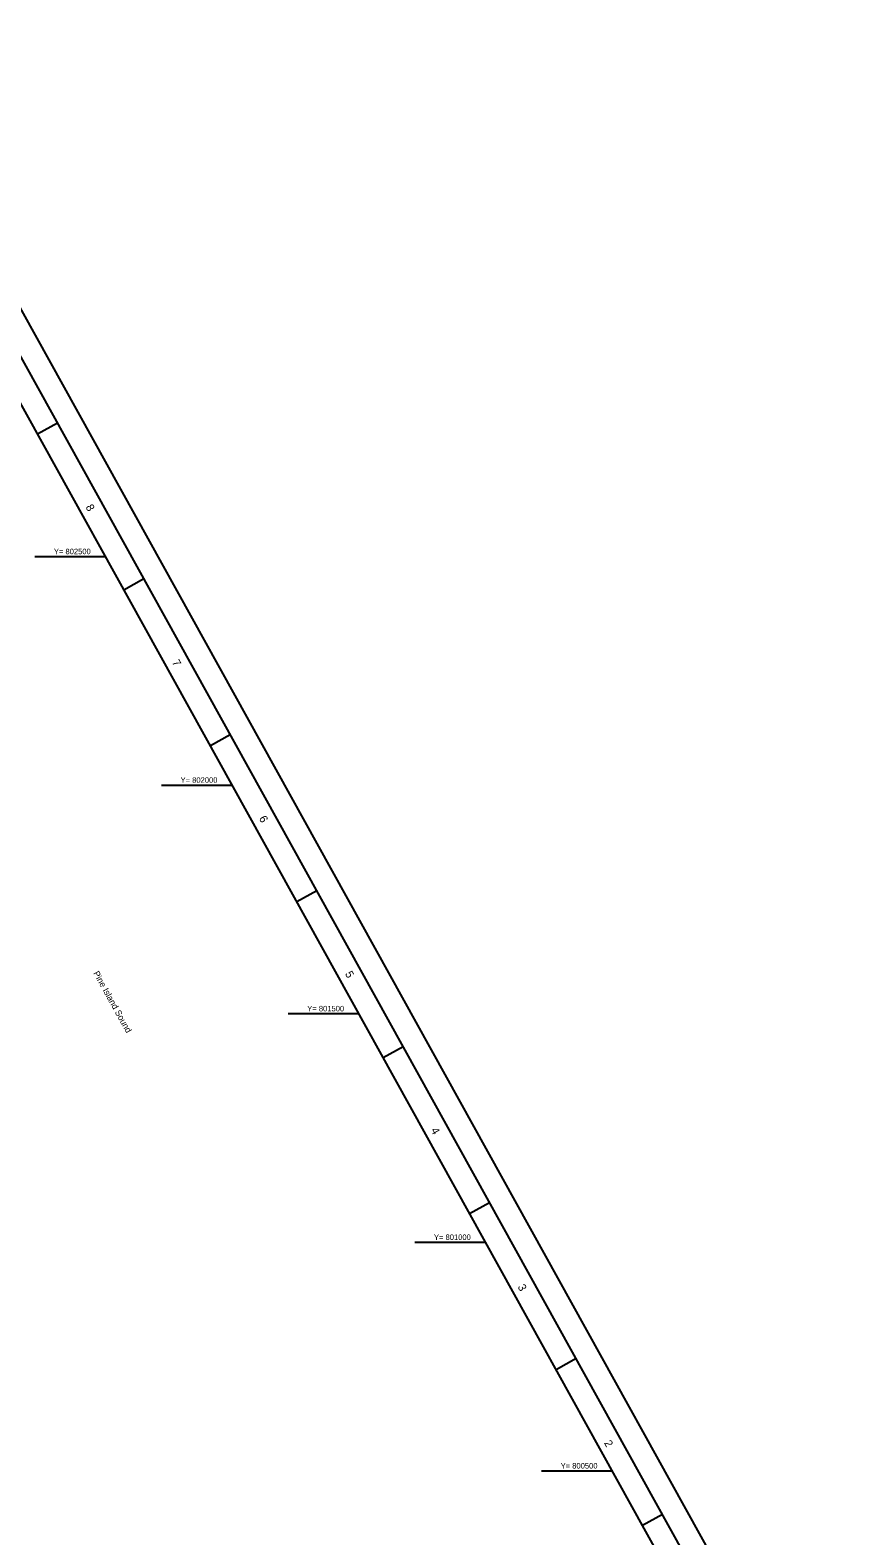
# Model space of a CAD drawing. Extents: x 601234 to 606341, y 798155 to 803651.
# Drawn here: x 604567 to 606341, y 800358 to 803651 of the extents above; entities that cross this region are included whole.
import ezdxf

# ---------------------------------------------------------------- set-up
doc = ezdxf.new("R2010")
doc.units = 0
for name, color, linetype in [('G-ANNO-NPLT', 7, 'Continuous'), ('G-ANNO-TTLB', 7, 'Continuous'), ('V-SITE-WATR', 7, 'Continuous'), ('V-TOPO-COOR-STAT', 7, 'Continuous')]:
    doc.layers.add(name, color=color, linetype=linetype)

msp = doc.modelspace()

# ---------------------------------------------------------------- linework, layer by layer
at = {"layer": 'G-ANNO-NPLT'}
msp.add_lwpolyline([(604207.8, 803651.4), (606341.2, 799803.3), (603367.7, 798154.7), (601234.2, 802002.9)], close=True, dxfattribs=at)
at = {"layer": 'G-ANNO-TTLB'}
for p, q in [((604627.1, 802791.9), (604583.4, 802767.7)), ((604627.1, 802791.9), (604583.4, 802767.7)), ((604816.2, 802450.9), (604772.5, 802426.6)), ((605005.3, 802109.8), (604961.6, 802085.5)), ((605194.4, 801768.7), (605150.7, 801744.4)), ((605383.5, 801427.6), (605339.8, 801403.3)), ((605572.6, 801086.5), (605528.9, 801062.3)), ((605761.7, 800745.4), (605718, 800721.2)), ((605950.8, 800404.3), (605907.1, 800380.1))]:
    msp.add_line(p, q, dxfattribs=at)
for points in [[(601302.2, 801983.4), (603387.1, 798222.7), (606273.3, 799822.7), (604188.3, 803583.4)], [(606205.3, 799842.2), (604205.2, 803449.9), (601406.6, 801898.3), (603406.6, 798290.7)]]:
    msp.add_lwpolyline(points, close=True, dxfattribs=at)
at = {"layer": 'V-TOPO-COOR-STAT'}
for p, q in [((604577.5, 802500), (604731.8, 802500)), ((604854.7, 802000), (605009, 802000)), ((605131.9, 801500), (605286.2, 801500)), ((605409.1, 801000), (605563.4, 801000)), ((605686.3, 800500), (605840.6, 800500))]:
    msp.add_line(p, q, dxfattribs=at)

# ---------------------------------------------------------------- texts
at = {"layer": 'G-ANNO-TTLB'}
for s, p in [('8', (604688.1, 802608.3)), ('7', (604877.2, 802268.7)), ('6', (605067.4, 801927.2)), ('5', (605255.7, 801587.4)), ('4', (605443.4, 801245.1)), ('3', (605633.3, 800902.4)), ('2', (605822.4, 800561.3))]:
    msp.add_text(s, height=17.5, rotation=299.0039, dxfattribs=at).set_placement(p)
at = {"layer": 'V-SITE-WATR'}
msp.add_text('Pine Island Sound', height=13.92, rotation=299.0039, dxfattribs=at).set_placement((604704.9, 801588.4))
at = {"layer": 'V-TOPO-COOR-STAT'}
for s, p in [('Y= 802500', (604619.3, 802505)), ('Y= 802000', (604896.5, 802005)), ('Y= 801500', (605173.7, 801505)), ('Y= 801000', (605450.9, 801005)), ('Y= 800500', (605728.1, 800505))]:
    msp.add_text(s, height=12, dxfattribs=at).set_placement(p)

doc.saveas('drawing.dxf')
